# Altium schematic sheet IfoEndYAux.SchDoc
size C; Engineer: Daniel Sigg; DocumentNumber: 8; SheetNumber: 32; SheetTotal: 33
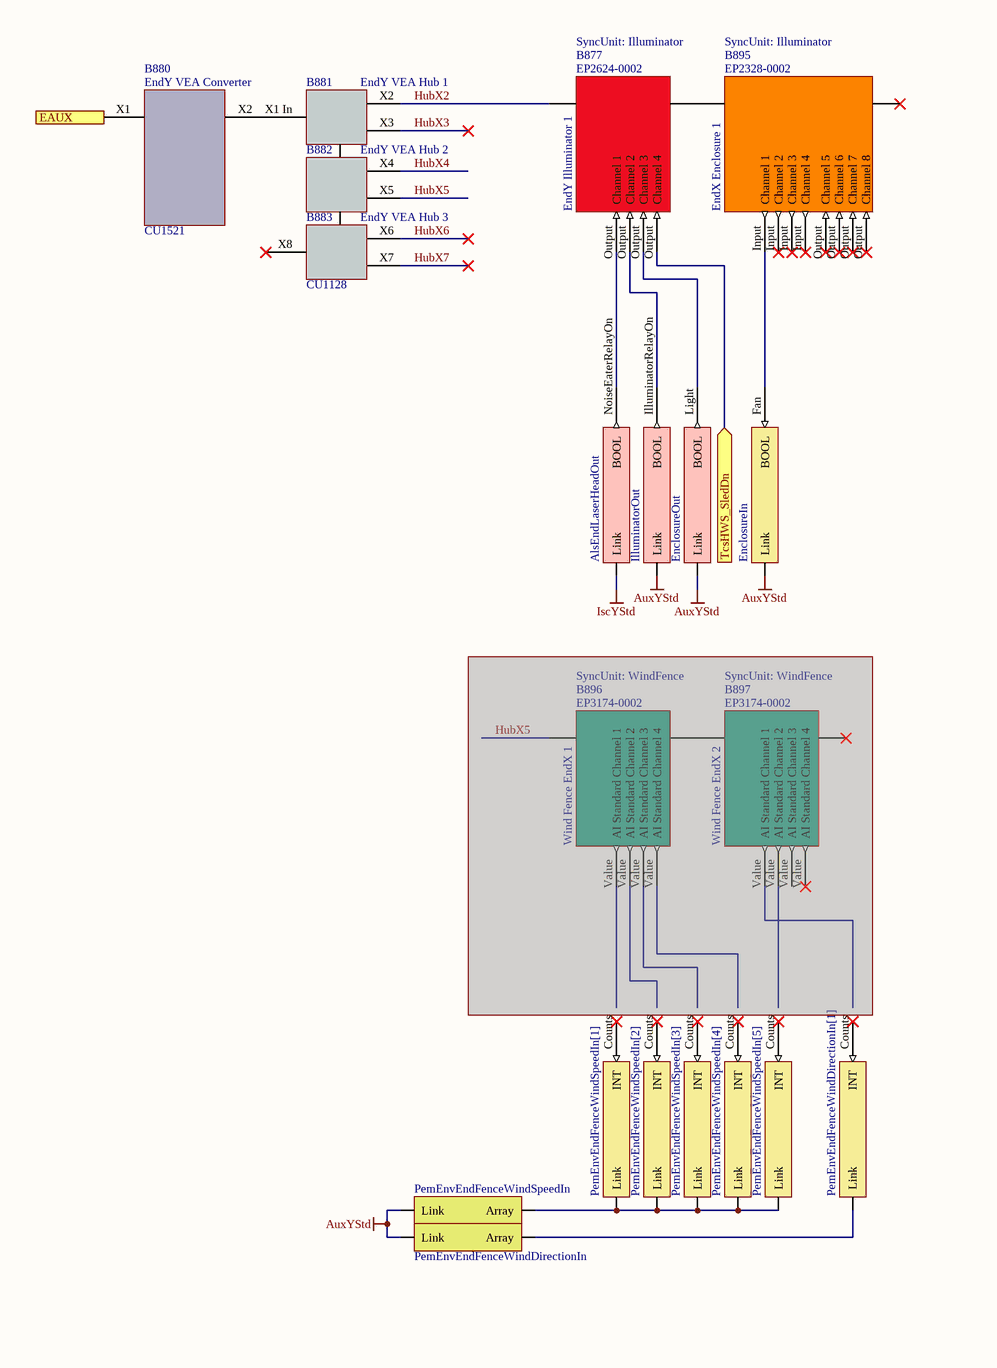
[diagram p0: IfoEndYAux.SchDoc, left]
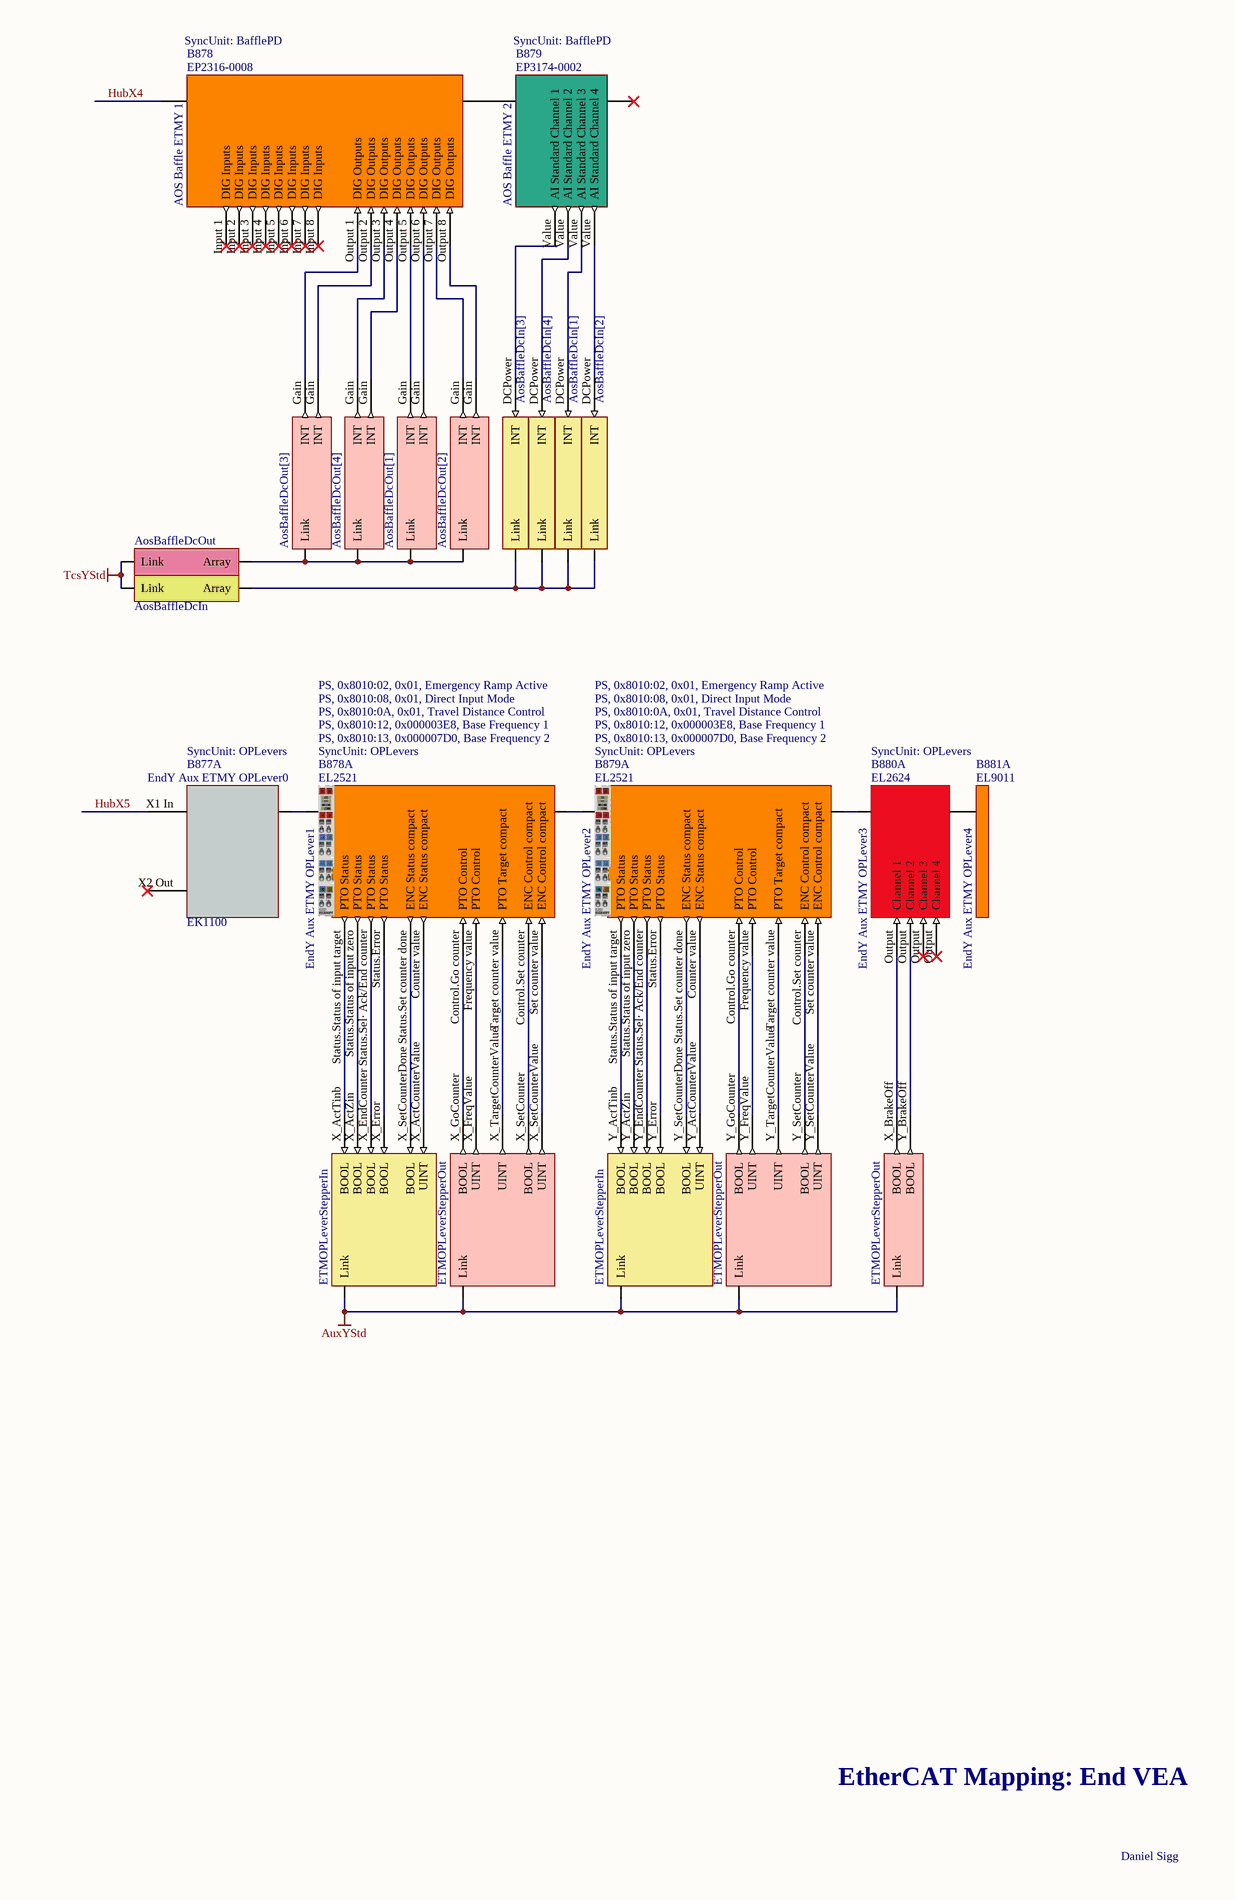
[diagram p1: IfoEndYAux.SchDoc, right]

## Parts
B877  EndY Illuminator 1  Part Number: EP2624-0002  SyncUnit: Illuminator  (mechanical)
B877A  EndY Aux ETMY OPLever0  SyncUnit: OPLevers  Part Number: EK1100  (mechanical)
B878  AOS Baffle ETMY 1  Part Number: EP2316-0008  SyncUnit: BafflePD  (mechanical)
B878A  EndY Aux ETMY OPLever1  SyncUnit: OPLevers  Part Number: EL2521  Init0Cmd: PS, 0x8010:02, 0x01, Emergency Ramp Active  Init1Cmd: PS, 0x8010:08, 0x01, Direct Input Mode  Init2Cmd: PS, 0x8010:0A, 0x01, Travel Distance Control  Init3Cmd: PS, 0x8010:12, 0x000003E8, Base Frequency 1  Init4Cmd: PS, 0x8010:13, 0x000007D0, Base Frequency 2  (mechanical)
B879  AOS Baffle ETMY 2  Part Number: EP3174-0002  SyncUnit: BafflePD  (mechanical)
B879A  EndY Aux ETMY OPLever2  SyncUnit: OPLevers  Part Number: EL2521  Init0Cmd: PS, 0x8010:02, 0x01, Emergency Ramp Active  Init1Cmd: PS, 0x8010:08, 0x01, Direct Input Mode  Init2Cmd: PS, 0x8010:0A, 0x01, Travel Distance Control  Init3Cmd: PS, 0x8010:12, 0x000003E8, Base Frequency 1  Init4Cmd: PS, 0x8010:13, 0x000007D0, Base Frequency 2  (mechanical)
B880  EndY VEA Converter  Part Number: CU1521  (mechanical)
B880A  EndY Aux ETMY OPLever3  SyncUnit: OPLevers  Part Number: EL2624  (mechanical)
B881  EndY VEA Hub 1  Part Number: CU1128  (mechanical)
B881A  EndY Aux ETMY OPLever4  Part Number: EL9011  (mechanical)
B882  EndY VEA Hub 2  (mechanical)
B883  EndY VEA Hub 3  (mechanical)
B895  EndX Enclosure 1  SyncUnit: Illuminator  Part Number: EP2328-0002  (mechanical)
B896  Wind Fence EndX 1  Part Number: EP3174-0002  SyncUnit: WindFence  (mechanical)  (masked out: inside a compile mask, not in the netlist)
B897  Wind Fence EndX 2  Part Number: EP3174-0002  SyncUnit: WindFence  (mechanical)  (masked out: inside a compile mask, not in the netlist)
V649  AlsEndLaserHeadOut  (part B of 2)  (no BOM)
V686  IlluminatorOut  (no BOM)
V686A  ETMOPLeverStepperIn  (parts A,B of 2)  (no BOM)
V687  AosBaffleDcOut[3]  (no BOM)
V687A  ETMOPLeverStepperOut  (parts A,B,C of 3)  (no BOM)
V688  AosBaffleDcOut[4]  (no BOM)
V689  AosBaffleDcOut[1]  (no BOM)
V690  AosBaffleDcOut[2]  (no BOM)
V691  AosBaffleDcIn[3]  (no BOM)
V692  AosBaffleDcIn[4]  (no BOM)
V693  AosBaffleDcIn[1]  (no BOM)
V694  AosBaffleDcIn[2]  (no BOM)
V695  AosBaffleDcOut  (no BOM)
V700  AosBaffleDcIn  (no BOM)
V707  EnclosureIn  (no BOM)
V708  PemEnvEndFenceWindSpeedIn[1]  (no BOM)
V709  PemEnvEndFenceWindSpeedIn[2]  (no BOM)
V710  PemEnvEndFenceWindSpeedIn[3]  (no BOM)
V711  PemEnvEndFenceWindSpeedIn[4]  (no BOM)
V712  PemEnvEndFenceWindSpeedIn[5]  (no BOM)
V713  PemEnvEndFenceWindDirectionIn[1]  (no BOM)
V714  PemEnvEndFenceWindSpeedIn  (no BOM)
V715  PemEnvEndFenceWindDirectionIn  (no BOM)
V716  EnclosureOut  (no BOM)

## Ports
EAUX, TcsHWS_SledDn (in)

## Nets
AuxYStd: V686.0(Link) V686A.0(Link) V686A.1(Link) V687A.0(Link) V687A.1(Link) V687A.2(Link) V707.1(Link) V714.?1(Link) V715.?1(Link) V716.?1(Link)
IscYStd: V649.1(Link)
TcsYStd: V695.?1(Link) V700.?1(Link)
EAUX: B880.X1(A) ; port EAUX
HubX2: B877.?2(A) B881.X2(D)
HubX3: B881.X3(B)
HubX4: B878.?2(A) B882.X4(D)
HubX5: B877A.X1_In(A) B882.X5(B)
HubX6: B883.X6(D)
HubX7: B883.X7(B)
TcsHWS_SledDn: B877.Output(Channel_4) ; port TcsHWS_SledDn
NetB877_?1: B877.?1(B) B895.?2(A)
NetB877_Output: B877.Output(Channel_1) V649.NoiseEaterRelayOn(BOOL)
NetB877_Output: B877.Output(Channel_2) V686.IlluminatorRelayOn(BOOL)  [a separate net that carries the same name]
NetB877_Output: B877.Output(Channel_3) V716.Light(BOOL)  [a separate net that carries the same name]
NetB877A_Ebus: B877A.Ebus(B) B878A.Ebus(A)
NetB878_?1: B878.?1(B) B879.?2(A)
NetB878_Output 1: B878.Output_1(DIG_Outputs) V687.Gain(INT)
NetB878_Output 2: B878.Output_2(DIG_Outputs) V687.Gain(INT)
NetB878_Output 3: B878.Output_3(DIG_Outputs) V688.Gain(INT)
NetB878_Output 4: B878.Output_4(DIG_Outputs) V688.Gain(INT)
NetB878_Output 5: B878.Output_5(DIG_Outputs) V689.Gain(INT)
NetB878_Output 6: B878.Output_6(DIG_Outputs) V689.Gain(INT)
NetB878_Output 7: B878.Output_7(DIG_Outputs) V690.Gain(INT)
NetB878_Output 8: B878.Output_8(DIG_Outputs) V690.Gain(INT)
NetB878A_Control.Go counter: B878A.Control.Go_counter(PTO_Control) V687A.X_GoCounter(BOOL)
NetB878A_Control.Set counter: B878A.Control.Set_counter(ENC_Control_compact) V687A.X_SetCounter(BOOL)
NetB878A_Counter value: B878A.Counter_value(ENC_Status_compact) V686A.X_ActCounterValue(UINT)
NetB878A_Ebus: B878A.Ebus(B) B879A.Ebus(A)
NetB878A_Frequency value: B878A.Frequency_value(PTO_Control) V687A.X_FreqValue(UINT)
NetB878A_Set counter value: B878A.Set_counter_value(ENC_Control_compact) V687A.X_SetCounterValue(UINT)
NetB878A_Status.Error: B878A.Status.Error(PTO_Status) V686A.X_Error(BOOL)
NetB878A_Status.Sel· Ack/End counter: B878A.Status.Sel·_Ack/End_counter(PTO_Status) V686A.X_EndCounter(BOOL)
NetB878A_Status.Set counter done: B878A.Status.Set_counter_done(ENC_Status_compact) V686A.X_SetCounterDone(BOOL)
NetB878A_Status.Status of input target: B878A.Status.Status_of_input_target(PTO_Status) V686A.X_ActTinb(BOOL)
NetB878A_Status.Status of input zero: B878A.Status.Status_of_input_zero(PTO_Status) V686A.X_ActZin(BOOL)
NetB878A_Target counter value: B878A.Target_counter_value(PTO_Target_compact) V687A.X_TargetCounterValue(UINT)
NetB879_Value: B879.Value(AI_Standard_Channel_1) V691.DCPower(INT)
NetB879_Value: B879.Value(AI_Standard_Channel_2) V692.DCPower(INT)  [a separate net that carries the same name]
NetB879_Value: B879.Value(AI_Standard_Channel_3) V693.DCPower(INT)  [a separate net that carries the same name]
NetB879_Value: B879.Value(AI_Standard_Channel_4) V694.DCPower(INT)  [a separate net that carries the same name]
NetB879A_Control.Go counter: B879A.Control.Go_counter(PTO_Control) V687A.Y_GoCounter(BOOL)
NetB879A_Control.Set counter: B879A.Control.Set_counter(ENC_Control_compact) V687A.Y_SetCounter(BOOL)
NetB879A_Counter value: B879A.Counter_value(ENC_Status_compact) V686A.Y_ActCounterValue(UINT)
NetB879A_Ebus: B879A.Ebus(B) B880A.Ebus(A)
NetB879A_Frequency value: B879A.Frequency_value(PTO_Control) V687A.Y_FreqValue(UINT)
NetB879A_Set counter value: B879A.Set_counter_value(ENC_Control_compact) V687A.Y_SetCounterValue(UINT)
NetB879A_Status.Error: B879A.Status.Error(PTO_Status) V686A.Y_Error(BOOL)
NetB879A_Status.Sel· Ack/End counter: B879A.Status.Sel·_Ack/End_counter(PTO_Status) V686A.Y_EndCounter(BOOL)
NetB879A_Status.Set counter done: B879A.Status.Set_counter_done(ENC_Status_compact) V686A.Y_SetCounterDone(BOOL)
NetB879A_Status.Status of input target: B879A.Status.Status_of_input_target(PTO_Status) V686A.Y_ActTinb(BOOL)
NetB879A_Status.Status of input zero: B879A.Status.Status_of_input_zero(PTO_Status) V686A.Y_ActZin(BOOL)
NetB879A_Target counter value: B879A.Target_counter_value(PTO_Target_compact) V687A.Y_TargetCounterValue(UINT)
NetB880_X2: B880.X2(B) B881.X1_In(A)
NetB880A_Ebus: B880A.Ebus(B) B881A.Ebus(A)
NetB880A_Output: B880A.Output(Channel_1) V687A.X_BrakeOff(BOOL)
NetB880A_Output: B880A.Output(Channel_2) V687A.Y_BrakeOff(BOOL)  [a separate net that carries the same name]
NetB881_Ebus: B881.Ebus(C) B882.Ebus(A)
NetB882_Ebus: B882.Ebus(C) B883.Ebus(A)
NetB895_Input: B895.Input(Channel_1) V707.Fan(BOOL)
NetV687_0: V687.0(Link) V688.0(Link) V689.0(Link) V690.0(Link) V695.?2(Array)
NetV691_1: V691.1(Link) V692.1(Link) V693.1(Link) V694.1(Link) V700.?2(Array)
NetV708_1: V708.1(Link) V709.1(Link) V710.1(Link) V711.1(Link) V712.1(Link) V714.?2(Array)
NetV713_1: V713.1(Link) V715.?2(Array)

Not connected (* = marked no-connect by the designer): B877A X2 Out(C)*; B878 Input 1(DIG_Inputs)* Input 2(DIG_Inputs)* Input 3(DIG_Inputs)* Input 4(DIG_Inputs)* Input 5(DIG_Inputs)* Input 6(DIG_Inputs)* Input 7(DIG_Inputs)* Input 8(DIG_Inputs)*; B879 ?1(B)*; B883 X8(C)*; B895 ?1(B)* Output(Channel_5)*; V708 Counts(INT)*; V709 Counts(INT)*; V710 Counts(INT)*; V711 Counts(INT)*; V712 Counts(INT)*; V713 Counts(INT)*

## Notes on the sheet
- EtherCAT Mapping: End VEA
- Daniel Sigg

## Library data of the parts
B877 = BoxEP2624-0002: EtherCAT Box EP2624-0002 4-channel relay output 25 V AC/30 V DC; BoxNextB: RHDAAVMB; BoxPrev: MEUQVVTX; PortPrevFull: 1115/D; PortPrevShort: D 'X2'; Fullname: TIID^End Y (EtherCAT)^EndY Link L0 (EK1501-0010)^EndY Link L6 (EK1521)^EndY VEA Hub 1 (CU1128)^EndY Illuminator 1 (EP2624-0002); BoxAddr: 1116; Disabled: False
B877A = CouplerEK1100: EtherCAT Coupler; BoxNextB: OTJFSRTT; BoxPrev: AODWNIGF; PortPrevFull: 1118/B; PortPrevShort: B 'X5'; Fullname: TIID^End Y (EtherCAT)^EndY Link L0 (EK1501-0010)^EndY Link L6 (EK1521)^EndY VEA Hub 1 (CU1128)^EndY VEA Hub 2 (CU1128-0001)^EndY Aux ETMY OPLever0 (EK1100); BoxPorts: Junction; BoxAddr: 1121; Disabled: False
B878 = BoxEP2316-0008: EtherCAT Box EP2316-0008 8 x digital input + 8 x digital output; BoxNextB: LGKOFLFC; BoxPrev: AODWNIGF; PortPrevFull: 1118/D; PortPrevShort: D 'X4'; Fullname: TIID^End Y (EtherCAT)^EndY Link L0 (EK1501-0010)^EndY Link L6 (EK1521)^EndY VEA Hub 1 (CU1128)^EndY VEA Hub 2 (CU1128-0001)^AOS Baffle ETMY 1 (EP2316-0008); BoxAddr: 1119; Disabled: False
B878A = TerminalEL2521: EtherCAT Terminal EL2521 1-channel pulse train output, incr. enc. simulation, RS422, 50 mA; BoxNextB: JKXDFGXR; BoxPrev: FWOESITH; PortPrevFull: 1121/B; PortPrevShort: B; Fullname: TIID^End Y (EtherCAT)^EndY Link L0 (EK1501-0010)^EndY Link L6 (EK1521)^EndY VEA Hub 1 (CU1128)^EndY VEA Hub 2 (CU1128-0001)^EndY Aux ETMY OPLever0 (EK1100)^EndY Aux ETMY OPLever1 (EL2521); BoxAddr: 1122; PDO Outputs: 0x1601,0x1604,0x1602; PDO Inputs: 0x1A01,0x1A02; Disabled: False
B879 = BoxEP3174-0002: EtherCAT Box EP3174-0002 4-channel analog input ±10 V or 0/4…20 mA, parameterisable, differential input, 16 bit; BoxPrev: XGFRIHOL; PortPrevFull: 1119/B; PortPrevShort: B; Fullname: TIID^End Y (EtherCAT)^EndY Link L0 (EK1501-0010)^EndY Link L6 (EK1521)^EndY VEA Hub 1 (CU1128)^EndY VEA Hub 2 (CU1128-0001)^AOS Baffle ETMY 2 (EP3174-0002); BoxAddr: 1120; Disabled: False
B879A = TerminalEL2521: EtherCAT Terminal EL2521 1-channel pulse train output, incr. enc. simulation, RS422, 50 mA; BoxNextB: EMQHRAPL; BoxPrev: OTJFSRTT; PortPrevFull: 1122/B; PortPrevShort: B; Fullname: TIID^End Y (EtherCAT)^EndY Link L0 (EK1501-0010)^EndY Link L6 (EK1521)^EndY VEA Hub 1 (CU1128)^EndY VEA Hub 2 (CU1128-0001)^EndY Aux ETMY OPLever0 (EK1100)^EndY Aux ETMY OPLever2 (EL2521); BoxAddr: 1123; PDO Outputs: 0x1601,0x1604,0x1602; PDO Inputs: 0x1A01,0x1A02; Disabled: False
B880 = MediaConverterFiberToCAT5: EtherCAT Media Converter; BoxType: Box; BoxNextB: MEUQVVTX; BoxPrev: NEQKDDQF; PortPrevFull: 1007/C; PortPrevShort: C 'X2 Out'; Fullname: TIID^End Y (EtherCAT)^EndY Link L0 (EK1501-0010)^EndY Link L6 (EK1521)^EndY VEA Converter (CU1521); BoxAddr: 1114; Disabled: False
B880A = TerminalEL2624: EtherCAT Terminal EL2624 4-channel relay output terminal 125 V AC/30 V DC; BoxNextB: ADYJCOAH; BoxPrev: JKXDFGXR; PortPrevFull: 1123/B; PortPrevShort: B; Fullname: TIID^End Y (EtherCAT)^EndY Link L0 (EK1501-0010)^EndY Link L6 (EK1521)^EndY VEA Hub 1 (CU1128)^EndY VEA Hub 2 (CU1128-0001)^EndY Aux ETMY OPLever0 (EK1100)^EndY Aux ETMY OPLever3 (EL2624); BoxAddr: 1124; Disabled: False
B881 = HubCU1128: EtherCAT Hub; BoxType: Box; BoxNextC: AODWNIGF; BoxNextD: AHWEXOKQ; BoxPrev: KUHNJRYY; PortPrevFull: 1114/B; PortPrevShort: B 'X2'; Fullname: TIID^End Y (EtherCAT)^EndY Link L0 (EK1501-0010)^EndY Link L6 (EK1521)^EndY VEA Hub 1 (CU1128); BoxPorts: Junction; BoxAddr: 1115; Disabled: False
B881A = TerminalEL9011: EtherCAT Terminal EL9011 End; BoxType: TerminalPassive; BoxPrev: EMQHRAPL; PortPrevShort: B; Fullname: TIID^End Y (EtherCAT)^EndY Link L0 (EK1501-0010)^EndY Link L6 (EK1521)^EndY VEA Hub 1 (CU1128)^EndY VEA Hub 2 (CU1128-0001)^EndY Aux ETMY OPLever0 (EK1100)^EndY Aux ETMY OPLever4 (EL9011); Disabled: False
B882 = HubCU1128-B: EtherCAT Hub subpart B; Part Number: CU1128-0001; BoxType: Box; BoxNextB: FWOESITH; BoxNextC: QJXOTRXP; BoxNextD: XGFRIHOL; BoxPrev: MEUQVVTX; PortPrevFull: 1115/C; PortPrevShort: C; Fullname: TIID^End Y (EtherCAT)^EndY Link L0 (EK1501-0010)^EndY Link L6 (EK1521)^EndY VEA Hub 1 (CU1128)^EndY VEA Hub 2 (CU1128-0001); BoxPorts: Junction; BoxAddr: 1118; Disabled: False
B883 = HubCU1128-C: EtherCAT Hub subpart C; Part Number: CU1128-0002; BoxType: Box; BoxPrev: AODWNIGF; PortPrevFull: 1118/C; Fullname: TIID^End Y (EtherCAT)^EndY Link L0 (EK1501-0010)^EndY Link L6 (EK1521)^EndY VEA Hub 1 (CU1128)^EndY VEA Hub 3 (CU1128-0002); BoxPorts: Junction; BoxAddr: 1125; Disabled: False
B895 = BoxEP2328-0002: EtherCAT Box EP2328-0002 4 x digital input and 4 x digital output 24 V DC; BoxPrev: AHWEXOKQ; PortPrevFull: 1116/B; PortPrevShort: B; Fullname: TIID^End Y (EtherCAT)^EndY Link L0 (EK1501-0010)^EndY Link L6 (EK1521)^EndY VEA Hub 1 (CU1128)^EndX Enclosure 1 (EP2328-0002); BoxAddr: 1117; Disabled: False
B896 B897 = BoxEP3174-0002: EtherCAT Box EP3174-0002 4-channel analog input ±10 V or 0/4…20 mA, parameterisable, differential input, 16 bit; Disabled: False
V649 = ALSLaser_ALSLaserOutStruct: ALSLaserOutStruct; BoxType: Variable; Instance: H1IscEndY Instance; PLC: H1IscEndY; Task: IscEStd
V686 = Illuminator_IlluminatorOutStruct: IlluminatorOutStruct; BoxType: Variable; Instance: H1AuxEndY Instance; PLC: H1AuxEndY; Task: AuxEStd
V686A = OPLever_OPLeverStepperInStruct: OPLeverStepperInStruct; BoxType: Variable; Instance: H1AuxEndY Instance; PLC: H1AuxEndY; Task: AuxEStd
V687-V690 = DCPower_DCPowerOutStruct: DCPowerOutStruct; BoxType: Variable; Instance: H1TcsEndY Instance; PLC: H1TcsEndY; Task: TcsEStd
V687A = OPLever_OPLeverStepperOutStruct: OPLeverStepperOutStruct; BoxType: Variable; Instance: H1AuxEndY Instance; PLC: H1AuxEndY; Task: AuxEStd
V691-V694 = DCPower_DCPowerInStruct: DCPowerInStruct; BoxType: Variable; Instance: H1TcsEndY Instance; PLC: H1TcsEndY; Task: TcsEStd
V695 = ArrayAggregatorOut: Array [1..4] Of DCPowerOutStruct; Instance: H1TcsEndY Instance; PLC: H1TcsEndY; Task: TcsEStd; Lower Bound: 1; Upper Bound: 4
V700 = ArrayAggregatorIn: Array [1..4] Of DCPowerInStruct; Instance: H1TcsEndY Instance; PLC: H1TcsEndY; Task: TcsEStd; Lower Bound: 1; Upper Bound: 4
V707 = Enclosure_EnclosureInStruct: EnclosureInStruct; BoxType: Variable; Instance: H1AuxEndY Instance; PLC: H1AuxEndY; Task: AuxEStd
V708-V712 = WindSpeed_WindSpeedInStruct: WindSpeedInStruct; BoxType: Variable; Instance: H1AuxEndY Instance; PLC: H1AuxEndY; Task: AuxEStd
V713 = WindDirection_WindDirectionInStruct: WindDirectionInStruct; BoxType: Variable; Instance: H1AuxEndY Instance; PLC: H1AuxEndY; Task: AuxEStd
V714 = ArrayAggregatorIn: Array [1..5] Of WindSpeedInStruct; Instance: H1AuxEndY Instance; PLC: H1AuxEndY; Task: AuxEStd; Lower Bound: 1; Upper Bound: 5
V715 = ArrayAggregatorIn: Array [1..1] Of WindDirectionInStruct; Instance: H1AuxEndY Instance; PLC: H1AuxEndY; Task: AuxEStd; Lower Bound: 1
V716 = Enclosure_EnclosureOutStruct: EnclosureOutStruct; BoxType: Variable; Instance: H1AuxEndY Instance; PLC: H1AuxEndY; Task: AuxEStd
